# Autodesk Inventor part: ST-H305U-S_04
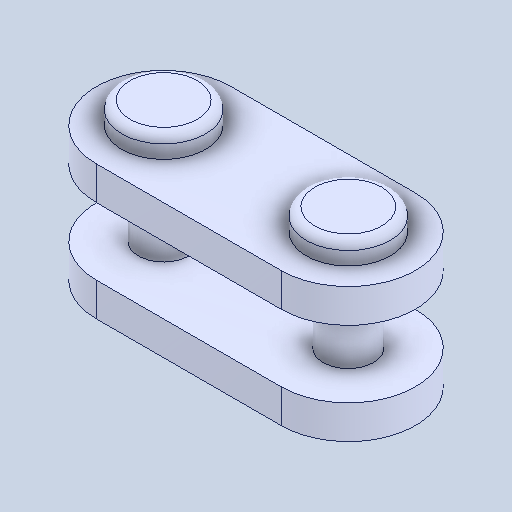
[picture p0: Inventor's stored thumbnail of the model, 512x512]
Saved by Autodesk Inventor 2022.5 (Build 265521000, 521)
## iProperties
Created: 2024-07
Part Number: ST-H305U-S_04
Material: 一般
Document SubType Name: Modeling
Designer: ImaoCorp
Density: 1 g/cm^3
Appearance: 既定
Author: ImaoCorp
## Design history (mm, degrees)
feature "ST-H305U-S_04"
node "ソリッド1"
